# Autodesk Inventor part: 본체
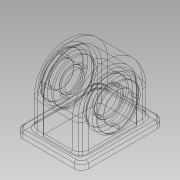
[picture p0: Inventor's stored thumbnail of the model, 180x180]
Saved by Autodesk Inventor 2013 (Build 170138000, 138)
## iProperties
Created: 2018-07
Part Number: 본체
Material: 11111111
Document SubType Name: Modeling
Designer: 05-01
Density: 7 g/cm^3
Mass: 2360.76 g
Surface Area: 768.298 cm^2
Volume: 337.252 cm^3
Author: 05-01
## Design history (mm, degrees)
sketch "스케치1"
  geometry: L1 (-47.5, 60)-(47.5, 60); L2 (47.5, 60)-(47.5, -60); L3 (47.5, -60)-(-47.5, -60); L4 (-47.5, -60)-(-47.5, 60); 3 further points
  constraints: 8 end point, 2 midpoint, 2 parallel, 1 horizontal, 1 horizontal alignment, 1 perpendicular, 1 vertical alignment
  dimensions: "d0" = 95 distance of L1.start L1.end; "d2" = 120 distance of L1.end L2.end
extrude "돌출1" new body sketch "스케치1" distance "d3" = 10; taper "d4" = 0 deg
sketch "스케치2"
  geometry: L1 (60, 0)-(-60, 0) reference; L2 (-51, 50)-(51, 50); L3 (51, 50)-(51, 0); L4 (51, 0)-(-51, 0); L5 (-51, 0)-(-51, 50); A1 r 51 centre (0, 50) between (51, 50) and (-51, 50); 1 further point
  constraints: 8 end point, 2 parallel, 2 point on circle, 1 centre point, 1 horizontal, 1 perpendicular, 1 point on line
  dimensions: "d5" = 102 diameter of A1; "d6" = 50 distance from line of L1 A1.centre
extrude "돌출2" join sketch "스케치2" stored distance "d7" = 74; taper "d8" = 0 deg
sketch "스케치3"
  geometry: L1 (-60, 0)-(60, 0) reference; L2 (42, 0)-(-42, 0); L3 (-42, 50)-(-42, 0); L4 (42, 50)-(42, 0); L5 (51, 50)-(51, 10) reference; A1 r 51 centre (0, 50) between (51, 50) and (-51, 50) reference; A2 r 42 centre (0, 50) between (42, 50) and (-42, 50); 1 further point
  constraints: 6 end point, 2 point on circle, 2 point on line, 1 centre point, 1 collinear, 1 perpendicular, 1 tangent, 1 vertical
  dimensions: "d9" = 9 radial gap between concentric circles of A1 A2; "d10" = 9 distance between parallel lines of L5 L4
extrude "돌출3" cut sketch "스케치3" stored distance "d11" = 56; taper "d12" = 0 deg
sketch "스케치4"
  geometry: C1 r 31 at (-50, 0); A1 r 42 centre (-50, 0) between (-50, 42) and (-50, -42) reference; 1 further point
  constraints: 1 centre point, 1 coincident
  dimensions: "d13" = 62 diameter of C1
extrude "돌출4" join sketch "스케치4" distance "d14" = 6; taper "d15" = 0 deg
sketch "스케치5"
  geometry: C1 r 31 at (50, 0); A1 r 51 centre (50, 0) between (50, -51) and (50, 51) reference; 1 further point
  constraints: 1 centre point, 1 coincident
  dimensions: "d16" = 62 diameter of C1
extrude "돌출5" join sketch "스케치5" distance "d17" = 5; taper "d18" = 0 deg
sketch "스케치6"
  geometry: C1 r 31 at (0, 0) reference; C2 r 17.5 at (0, 0); 1 further point
  constraints: 1 centre point, 1 coincident
  dimensions: "d19" = 35 diameter of C2
extrude "돌출6" cut sketch "스케치6" distance "d20" = 15; taper "d21" = 0 deg
hole "구멍1" diameter "d24" = 29; stored, may be unused: countersink angle "d28" = 90 deg, drill point angle "d30" = 0 deg; dims "d22" = 10, "d23" = 10, "d25" = 6, "d26" = 4, "d27" = 2, "d29" = 5
hole "구멍3" diameter "d45" = 42; stored, may be unused: countersink angle "d49" = 90 deg, drill point angle "d51" = 0 deg; dims "d43" = 10, "d44" = 10, "d46" = 6, "d47" = 4, "d48" = 2, "d50" = 15
hole "구멍4" diameter "d54" = 36; stored, may be unused: countersink angle "d58" = 90 deg, drill point angle "d60" = 0 deg; dims "d52" = 10, "d53" = 10, "d55" = 6, "d56" = 4, "d57" = 2, "d59" = 5
fillet "모깎기1" dims "d61" = 12
fillet "모깎기2" dims "d62" = 3
fillet "모깎기3" dims "d63" = 10
fillet "모깎기4" dims "d64" = 3
sketch "스케치9"
  geometry: C1 r 17.5 at (0, 0) reference; 2 further points
  dimensions: "d65" = 26 distance of point (26, 0) C1.centre
hole "구멍5" sketch "스케치9" at (26, 0) diameter "d66" = 3.242; stored, may be unused: countersink angle "d70" = 90 deg, drill point angle "d72" = 118 deg; dims "d67" = 8, "d68" = 4, "d69" = 2, "d71" = 10
chamfer "모따기1" distance "d76" = 1; stored, may be unused: second distance "d77" = 2, angle "d78" = 45 deg
fillet "모깎기5" dims "d79" = 0.3, "d80" = 0.6
node "솔리드1"
mirror "대칭3"
pattern_circular "원형 패턴1" dims angle "d74" = 360 deg
mirror "대칭4"
